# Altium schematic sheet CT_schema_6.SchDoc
size 254 x 194 mm
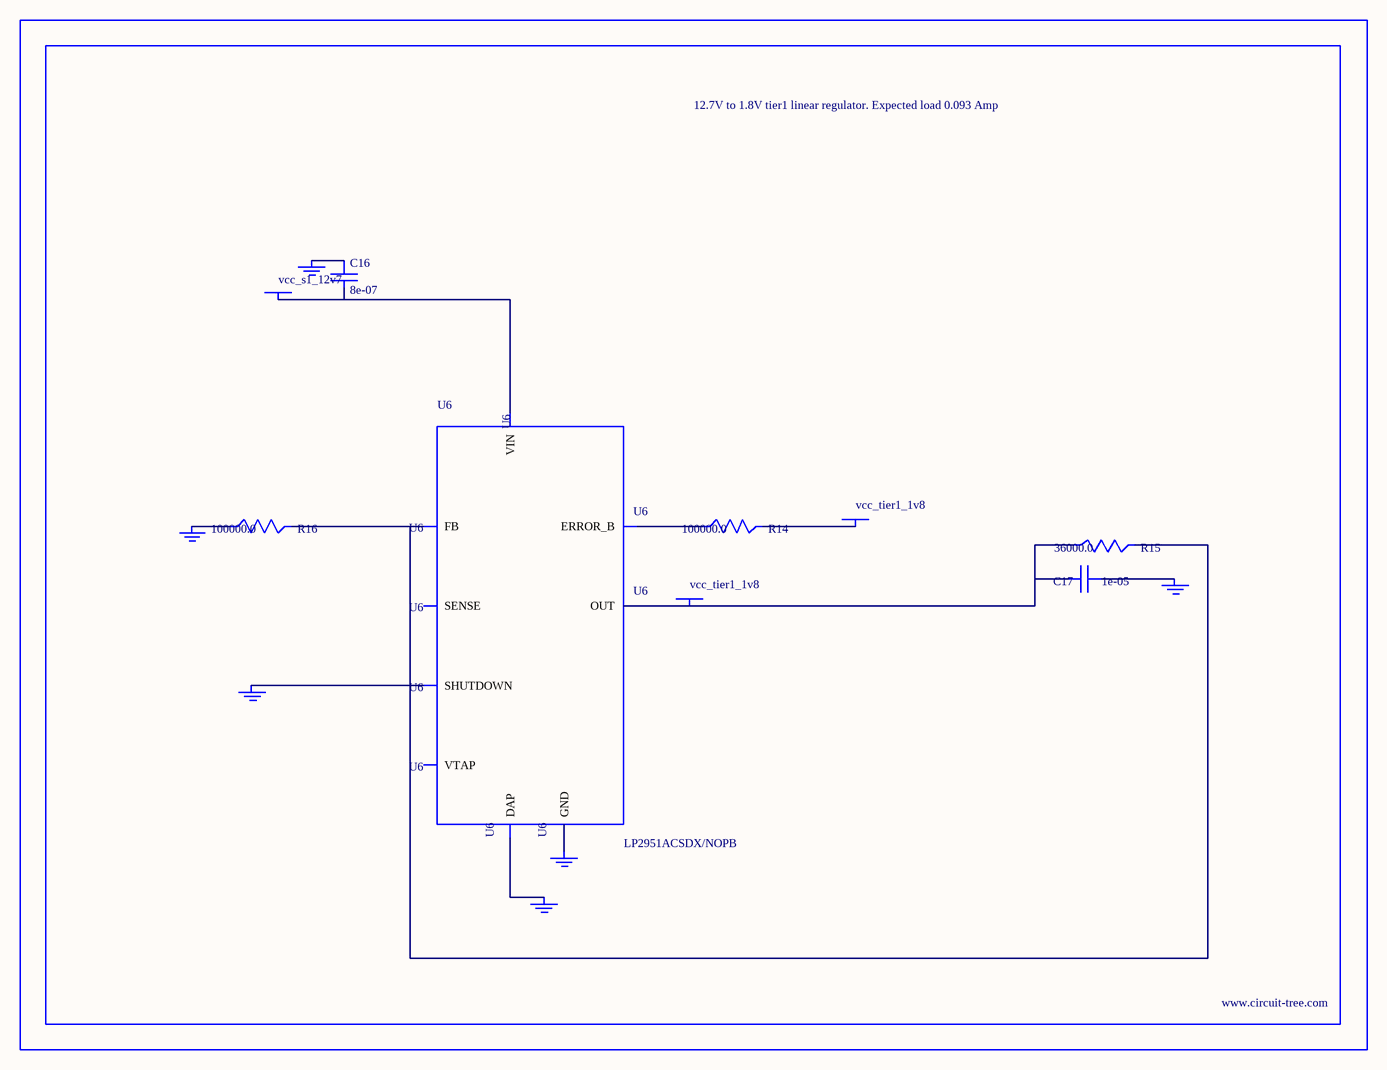
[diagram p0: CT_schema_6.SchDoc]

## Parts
BORDER5  (no value)
C16  8e-07  [R0603]
C17  1e-05  [C0805]
GND_INSTANCE_5_0  (no value)
GND_INSTANCE_5_1  (no value)
GND_INSTANCE_5_2  (no value)
GND_INSTANCE_5_3  (no value)
GND_INSTANCE_5_4  (no value)
GND_INSTANCE_5_5  (no value)
POWER_INSTANCE_5_0  vcc_tier1_1v8
POWER_INSTANCE_5_1  vcc_s1_12v7
POWER_INSTANCE_5_2  vcc_tier1_1v8
R14  100000.0  [R0603]
R15  36000.0  [R0603]
R16  100000.0  [R0603]
U6  LP2951ACSDX/NOPB  [WSON-8]

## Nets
NetC16_1: C16.1 GND_INSTANCE_5_3.0(GND)
NetC16_2: C16.2 POWER_INSTANCE_5_1.0(PWR) U6.8(VIN)
NetC17_1: C17.1 GND_INSTANCE_5_0.0(GND)
NetC17_2: C17.2 POWER_INSTANCE_5_2.0(PWR) R15.1 U6.1(OUT)
NetGND_INSTANCE_5_1_0: GND_INSTANCE_5_1.0(GND) U6.3(SHUTDOWN)
NetGND_INSTANCE_5_2_0: GND_INSTANCE_5_2.0(GND) R16.1
NetGND_INSTANCE_5_4_0: GND_INSTANCE_5_4.0(GND) U6.PAD(DAP)
NetGND_INSTANCE_5_5_0: GND_INSTANCE_5_5.0(GND) U6.4(GND)
NetPOWER_INSTANCE_5_0_0: POWER_INSTANCE_5_0.0(PWR) R14.2
NetR14_1: R14.1 U6.5(ERROR_B)
NetR15_2: R15.2 R16.2 U6.7(FB)

Not connected (* = marked no-connect by the designer): U6 2(SENSE) 6(VTAP)

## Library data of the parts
BORDER5 = BORDER_PAGE5
C16 = C16
C17 = GRM219R60J106ME19D
GND_INSTANCE_5_0-GND_INSTANCE_5_5 = GND
POWER_INSTANCE_5_0-POWER_INSTANCE_5_2 = PWR
R14 R16 = RC0603JR-07100KL
R15 = RC0603JR-0736KL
